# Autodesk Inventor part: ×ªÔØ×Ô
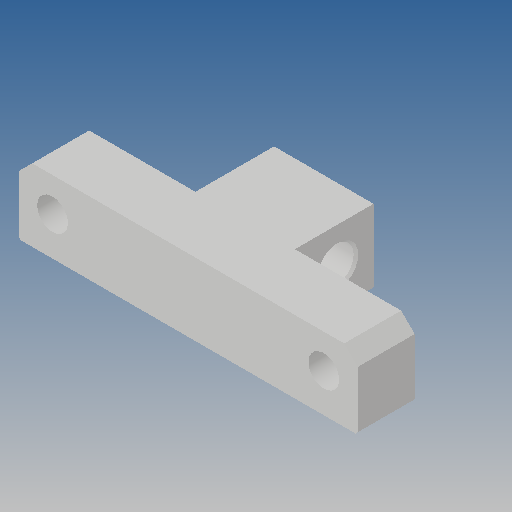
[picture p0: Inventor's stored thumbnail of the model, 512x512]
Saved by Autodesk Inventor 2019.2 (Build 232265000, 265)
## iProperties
Created: 2013-07
Part Number: ×ªÔØ×Ô
Material: Ogólny
Document SubType Name: Modeling
Designer: CADENGINEERING4
Density: 1 g/cm^3
Appearance: Domyślna
Author: CADENGINEERING4
Revision Number: ÈÎºÎ
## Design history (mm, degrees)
feature "µ¹½Ç2"
node "Bryła1"
